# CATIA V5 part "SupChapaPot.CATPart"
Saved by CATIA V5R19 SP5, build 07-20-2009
Part number: SuportePot
Bounding box of the stored display mesh (mm): x -17.5 to 17.5, y -20 to 10, z 0 to 22
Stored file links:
  Z:\UA\ATLAS\atlascar\ServoPiloto\dir\suportePotenciometro\V2\potenciometro\SupChapaPot.CATPart
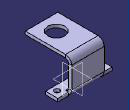
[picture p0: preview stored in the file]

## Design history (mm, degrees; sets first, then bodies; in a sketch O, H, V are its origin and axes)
SheetMetalParameters1: Thickness 2, BendRadius 2, KFactor 0.325257 {= log(min(100,max(20*SheetMetalParameters1.BendRadius,SheetMetalParameters1.Thickness)/SheetMetalParameters1.Thickness))/log(100)/2}, ReliefRadialLength 1, ReliefAxialLength 2, MinimumBendRadius 0
Body1 (main body)
  Sketch1 on xy-plane, origin (0, 0, 0), H (1, 0, 0), V (0, 1, 0)
    point P1 (-17.5, 0)
    line L1 (-17.5, 0) -> (17.5, 0)
    line L2 (17.5, 0) -> (17.5, 8)
    line L3 (17.5, 8) -> (-17.5, 8)
    line L4 (-17.5, 8) -> (-17.5, 0)
    axis line L5 (-24.2245, 3.5) -> (25.3364, 3.5)
    circle A1 centre (-13.5, 3.5) radius 1.75
    point P7 (-13.5, 3.5)
    circle A2 centre (13.5, 3.5) radius 1.75
    point P8 (13.5, 3.5)
    distance L2 L4 = 35
    distance V L4 = 17.5 {= Sketch1.distance(L2 L4) /2}
    distance L3 L1 = 8
    radius A1 = 1.75
    radius A2 = 1.75 {= Sketch1.radius(A1)}
    distance L5 L1 = 3.5 {= Sketch1.radius(A2) * 2}
    distance P8 P7 = 27
    distance P7 V = 13.5 {= Sketch1.distance(P8 P7) /2}
    coincidence: P1 H, P7 L5, P8 L5
    horizontal: L1 H, L3 H, L5 H
    vertical: L2 V, L4 V
  Wall1: Thickness 2, Profile Sketch1
  d_NewWallOnEdge1: NewWallOnEdge_Edge edge [face of Wall1 | face of Wall1], NewWallOnEdge_Length 20, NewWallOnEdge_HeightLimitOffset 0, NewWallOnEdge_WidthOffset1 -7, NewWallOnEdge_WidthOffset2 -7, NewWallOnEdge_Angle 90, NewWallOnEdge_BendRadiusValue 2 {= SheetMetalParameters1.BendRadius}, NewWallOnEdge_BendTable SheetMetalParameters1, KFacteur 0.325257 {= log(min(100,max(20*d_NewWallOnEdge1.Radius,SheetMetalParameters1.Thickness)/SheetMetalParameters1.Thickness))/log(100)/2}
  d_NewWallOnEdge2: NewWallOnEdge_Length 30, NewWallOnEdge_Edge edge [face of d_NewWallOnEdge1 | face of d_NewWallOnEdge1], NewWallOnEdge_HeightLimitOffset 0, NewWallOnEdge_WidthOffset1 0, NewWallOnEdge_WidthOffset2 0, NewWallOnEdge_Angle 90, NewWallOnEdge_BendRadiusValue 2 {= SheetMetalParameters1.BendRadius}, NewWallOnEdge_BendTable SheetMetalParameters1, KFacteur 0.325257 {= log(min(100,max(20*d_NewWallOnEdge2.Radius,SheetMetalParameters1.Thickness)/SheetMetalParameters1.Thickness))/log(100)/2}
  Sketch2 on face of d_NewWallOnEdge2, origin (-3.4624, -10.635, 22), H (1, 0, 0), V (0, 1, 0)
    point P1 (3.9624, 0.635)
    reference intersected line E1 through (0, 20.635) direction (-1, 0) from face of d_NewWallOnEdge1
    reference intersected line E2 (13.9624, 16.635) -> (13.9624, -9.365) from face of d_NewWallOnEdge2
    distance E1 P1 = 20
    distance P1 E2 = 10
  Hole1: placed by Sketch2, at (0.5, -10, 22) direction (0, 0, -1), diameter 11, through (limit type 6)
